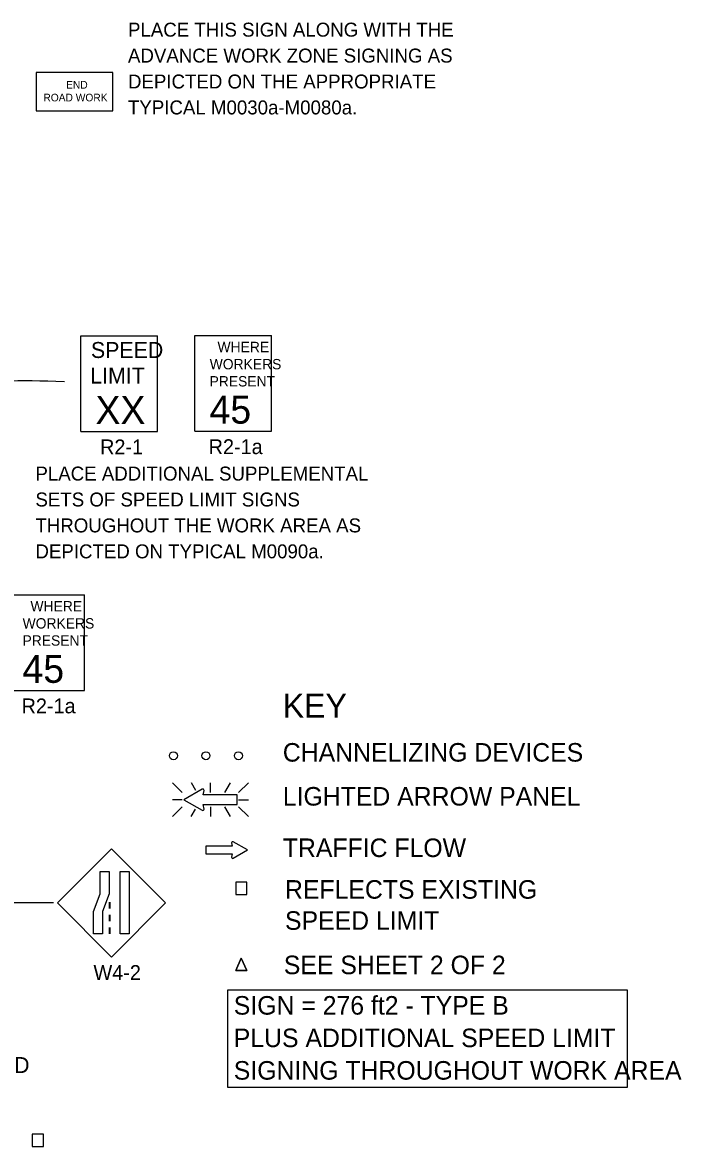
# Model space of a CAD drawing. Extents: x 16726 to 18475, y 5729 to 6921.
# Drawn here: x 17111 to 17442, y 6356 to 6920 of the extents above; entities that cross this region are included whole.
import ezdxf

# ---------------------------------------------------------------- set-up
doc = ezdxf.new("R2010")
doc.units = 0
for name, color, linetype in [('MT_SCRATCH_LEVEL_E', 7, 'Continuous'), ('TRAFFIC_SIGNS_PR', 7, 'Continuous'), ('TYPICAL_TEXT_DIMEN_EX', 7, 'Continuous'), ('TYPICAL_TEXT_DIMEN_PR', 7, 'Continuous')]:
    doc.layers.add(name, color=color, linetype=linetype)

msp = doc.modelspace()

# ---------------------------------------------------------------- linework, layer by layer
at = {"layer": 'MT_SCRATCH_LEVEL_E'}
for p, q in [((17216.38, 6506.78), (17203.12, 6506.78)), ((17203.12, 6506.78), (17203.12, 6503.04)), ((17216.38, 6506.78), (17203.12, 6506.78)), ((17203.12, 6506.78), (17203.12, 6503.04)), ((17216.06, 6508.55), (17216.38, 6506.78)), ((17216.06, 6508.55), (17216.38, 6506.78)), ((17223.99, 6504.93), (17216.75, 6509.04)), ((17223.99, 6504.93), (17216.75, 6509.04)), ((17216.75, 6500.78), (17223.99, 6504.93)), ((17216.75, 6500.78), (17223.99, 6504.93)), ((17203.12, 6503.04), (17216.38, 6503.04)), ((17203.12, 6503.04), (17216.38, 6503.04)), ((17216.38, 6503.04), (17216.06, 6501.26)), ((17216.38, 6503.04), (17216.06, 6501.26))]:
    msp.add_line(p, q, dxfattribs=at)
for centre, start, end in [((17216.52, 6508.63), 60.4248, 189.9638), ((17216.52, 6508.63), 60.4248, 189.9638), ((17216.52, 6501.19), 170.0362, 299.7731), ((17216.52, 6501.19), 170.0362, 299.7731)]:
    msp.add_arc(centre, 0.463, start, end, dxfattribs=at)
at = {"layer": 'TRAFFIC_SIGNS_PR'}
for p, q in [((17140.48, 6762.8), (17178.88, 6762.8)), ((17140.48, 6714.8), (17140.48, 6762.8)), ((17178.88, 6714.8), (17178.88, 6762.8)), ((17197.67, 6762.89), (17236.07, 6762.89)), ((17197.67, 6714.89), (17197.67, 6762.89)), ((17236.07, 6714.89), (17236.07, 6762.89)), ((17140.48, 6714.8), (17178.88, 6714.8)), ((17197.67, 6714.89), (17236.07, 6714.89)), ((17103.87, 6632.9), (17142.27, 6632.9)), ((17142.27, 6584.9), (17142.27, 6632.9)), ((17103.87, 6584.9), (17142.27, 6584.9)), ((17186.33, 6538.65), (17191.26, 6533.72)), ((17198.09, 6534.83), (17195.88, 6538.65)), ((17205.41, 6533.72), (17205.41, 6538.65)), ((17212.65, 6533.72), (17215.49, 6538.65)), ((17219.56, 6533.72), (17224.5, 6538.65)), ((17191.26, 6530.16), (17186.33, 6530.16)), ((17219.56, 6530.16), (17224.5, 6530.16)), ((17186.33, 6521.67), (17191.26, 6526.61)), ((17195.84, 6521.67), (17197.95, 6525.33)), ((17205.41, 6526.61), (17205.41, 6521.67)), ((17215.54, 6521.67), (17212.69, 6526.61)), ((17219.56, 6526.61), (17224.5, 6521.67)), ((17155.83, 6505.5), (17128.68, 6478.35)), ((17182.98, 6478.35), (17155.83, 6505.5)), ((17128.68, 6478.35), (17155.83, 6451.2)), ((17154.58, 6478.84), (17154.58, 6475.64)), ((17154.98, 6478.84), (17154.98, 6475.64)), ((17155.83, 6451.2), (17182.98, 6478.35)), ((17154.58, 6472.44), (17154.58, 6469.24)), ((17154.98, 6472.44), (17154.98, 6469.24)), ((17154.58, 6466.04), (17154.58, 6462.84)), ((17154.98, 6466.04), (17154.98, 6462.84))]:
    msp.add_line(p, q, dxfattribs=at)
for points in [[(17118.06, 6875.6), (17156.46, 6875.6), (17156.46, 6894.8), (17118.06, 6894.8)], [(17154.58, 6494.09), (17154.58, 6482.91), (17151.24, 6474.02), (17151.24, 6462.84), (17146.74, 6462.84), (17146.74, 6474.02), (17150.09, 6482.91), (17150.09, 6494.09)], [(17164.72, 6494.09), (17164.72, 6462.84), (17160.22, 6462.84), (17160.22, 6494.09)], [(17218.09, 6482.55), (17223.69, 6482.55), (17223.69, 6488.72), (17218.09, 6488.72)], [(17116.09, 6356.23), (17121.68, 6356.23), (17121.68, 6362.4), (17116.09, 6362.4)]]:
    msp.add_lwpolyline(points, close=True, dxfattribs=at)
for points in [[(17201.34, 6535.44), (17192.05, 6530.16), (17201.34, 6524.84)], [(17202.21, 6525.47), (17201.81, 6527.74), (17218.83, 6527.74), (17218.83, 6532.54), (17201.81, 6532.54), (17202.22, 6534.82)], [(17220.89, 6450.66), (17218.09, 6444.49)], [(17218.09, 6444.49), (17220.89, 6450.66)], [(17223.69, 6444.49), (17220.89, 6450.66)], [(17220.89, 6450.66), (17223.69, 6444.49)], [(17218.09, 6444.49), (17223.69, 6444.49)], [(17223.69, 6444.49), (17218.09, 6444.49)]]:
    msp.add_lwpolyline(points, dxfattribs=at)
for centre in [(17186.89, 6552.19), (17203.19, 6552.19), (17219.49, 6552.19)]:
    msp.add_circle(centre, 2, dxfattribs=at)
for centre, radius, start, end in [((17201.63, 6534.91), 0.598, 350.7308, 118.8916), ((17201.63, 6525.37), 0.597, 241.4833, 9.9593)]:
    msp.add_arc(centre, radius, start, end, dxfattribs=at)
at = {"layer": 'TYPICAL_TEXT_DIMEN_EX'}
msp.add_lwpolyline([(17214.13, 6434.78), (17414.38, 6434.78), (17414.38, 6385.86), (17214.13, 6385.86)], close=True, dxfattribs=at)
at = {"layer": 'TYPICAL_TEXT_DIMEN_PR'}
msp.add_line((17126.81, 6478.44), (17080.85, 6478.44), dxfattribs=at)
msp.add_open_spline([(17052.38, 6720.3), (17109.65, 6719.38), (17109.65, 6730.13), (17074.74, 6730.13), (17074.74, 6739.18), (17108.94, 6740.94), (17132.27, 6739.83)], degree=3, dxfattribs=at)

# ---------------------------------------------------------------- texts
at = {"layer": 'TRAFFIC_SIGNS_PR'}
for s, height, p in [('PLACE THIS SIGN ALONG WITH THE', 7, (17164.08, 6912.8)), ('ADVANCE WORK ZONE SIGNING AS', 7, (17164.08, 6899.8)), ('DEPICTED ON THE APPROPRIATE', 7, (17164.08, 6886.8)), ('END', 3.831, (17133.06, 6886.73)), ('ROAD WORK', 3.831, (17121.67, 6880.34)), ('TYPICAL M0030a-M0080a.', 7, (17164.08, 6873.8)), ('SPEED', 8, (17145.51, 6751.66)), ('WHERE', 5.2, (17208.98, 6754.57)), ('WORKERS', 5.2, (17205.06, 6745.97)), ('LIMIT', 8, (17145.18, 6738.86)), ('PRESENT', 5.2, (17204.99, 6737.37)), ('XX', 14.031, (17147.79, 6718.56)), ('45', 14.031, (17204.98, 6718.74)), ('R2-1', 7.44, (17150.09, 6703.36)), ('R2-1a', 7.44, (17204.53, 6703.45)), ('PLACE ADDITIONAL SUPPLEMENTAL', 7, (17117.67, 6690.19)), ('SETS OF SPEED LIMIT SIGNS', 7, (17117.67, 6677.19)), ('THROUGHOUT THE WORK AREA AS', 7, (17117.67, 6664.19)), ('DEPICTED ON TYPICAL M0090a.', 7, (17117.67, 6651.19)), ('WHERE', 5.2, (17115.18, 6624.58)), ('WORKERS', 5.2, (17111.25, 6615.98)), ('PRESENT', 5.2, (17111.19, 6607.38)), ('45', 14.031, (17111.18, 6588.75)), ('R2-1a', 7.44, (17110.72, 6573.46)), ('W4-2', 7.44, (17146.79, 6439.76)), ('SPEED', 8, (17078.44, 6393.09))]:
    msp.add_text(s, height=height, dxfattribs=at).set_placement(p)
at = {"layer": 'TYPICAL_TEXT_DIMEN_EX'}
for s, height, p in [('KEY', 12, (17241.73, 6571.3)), ('CHANNELIZING DEVICES', 9.3, (17241.73, 6549.25)), ('LIGHTED ARROW PANEL', 9.3, (17241.73, 6527.2)), ('TRAFFIC FLOW', 9.3, (17241.73, 6501.4)), ('REFLECTS EXISTING', 9.3, (17242.82, 6480.5)), ('SPEED LIMIT', 9.3, (17242.82, 6464.9)), ('SEE SHEET 2 OF 2', 9.3, (17242.24, 6442.65)), ('SIGN = 276 ft2 - TYPE B', 9.3, (17217.14, 6422.37)), ('PLUS ADDITIONAL SPEED LIMIT', 9.3, (17217.14, 6406.07)), ('SIGNING THROUGHOUT WORK AREA', 9.3, (17217.14, 6389.77))]:
    msp.add_text(s, height=height, dxfattribs=at).set_placement(p)

doc.saveas('drawing.dxf')
